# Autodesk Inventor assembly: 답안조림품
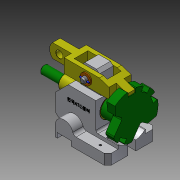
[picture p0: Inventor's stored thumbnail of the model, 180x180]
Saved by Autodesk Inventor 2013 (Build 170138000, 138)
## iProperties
Created: 2016-11
Part Number: 답안조림품
Document SubType Name: Assembly
Designer: default
Author: default
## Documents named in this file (8)
- C:\Documents and Settings\default\바탕 화면\461108V1010\답안조림품.iam
- C:\Documents and Settings\default\바탕 화면\461108V1010\1-본체.ipt
- C:\Documents and Settings\default\바탕 화면\461108V1010\분할축.ipt
- C:\Documents and Settings\default\바탕 화면\461108V1010\부시.ipt
- C:\Documents and Settings\default\바탕 화면\461108V1010\클레비스핀.ipt
- C:\Documents and Settings\default\바탕 화면\461108V1010\분할대.ipt
- C:\Documents and Settings\default\바탕 화면\461108V1010\와셔.ipt
- C:\Documents and Settings\default\바탕 화면\461108V1010\원통형핀.ipt
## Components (1 placed, 1 different names)
1. 1-본체:1
